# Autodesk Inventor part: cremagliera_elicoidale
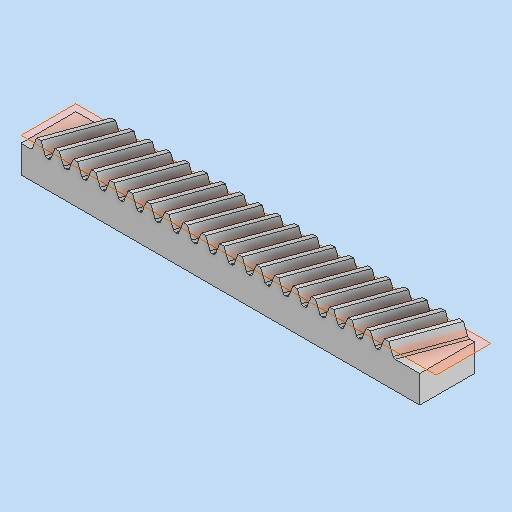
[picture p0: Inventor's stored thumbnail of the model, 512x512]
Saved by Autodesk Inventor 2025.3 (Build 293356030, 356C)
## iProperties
Created: 2025-12
Part Number: cremagliera_elicoidale
Material: Generico
Document SubType Name: Modeling
Designer: R5800u
Density: 1 g/cm^3
Appearance: Default
Author: R5800u
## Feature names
1. Estrusione1 [Extrusion]
2. Sweep2
3. Raccordo2 [Fillet]
4. Serie rettangolare2 [Rectangular Pattern]
5. Estrusione2 [Extrusion]
6. Estrusione3 [Extrusion]
7. Estrusione4 [Extrusion]
8. Serie rettangolare3 [Rectangular Pattern]
9. Speculare1 [Mirror]
10. Estrusione5 [Extrusion]
## Parameters: d1 = 1.25 mm, d3 = 3.69536 mm, d5 = -20 deg, d13 = 2 mm, d15 = 5 mm, d16 = 0, d21 = 2.25 mm, d22 = 0, d23 = 0, d24 = 0.38 mm, d27 = 3.34321 mm, d28 = 1.25 mm, d29 = 5 mm, d30 = 0, d31 = 2 mm, d32 = 0, d33 = 1.8 mm, d34 = 4 mm, d35 = 0, d36 = 8 mm, d37 = 2.5 mm, d38 = 4 mm, d39 = 0, d42 = 15 mm, d43 = 12 mm, d44 = 2.5 mm, d46 = 0
